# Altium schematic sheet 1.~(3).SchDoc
size 609 x 444 mm
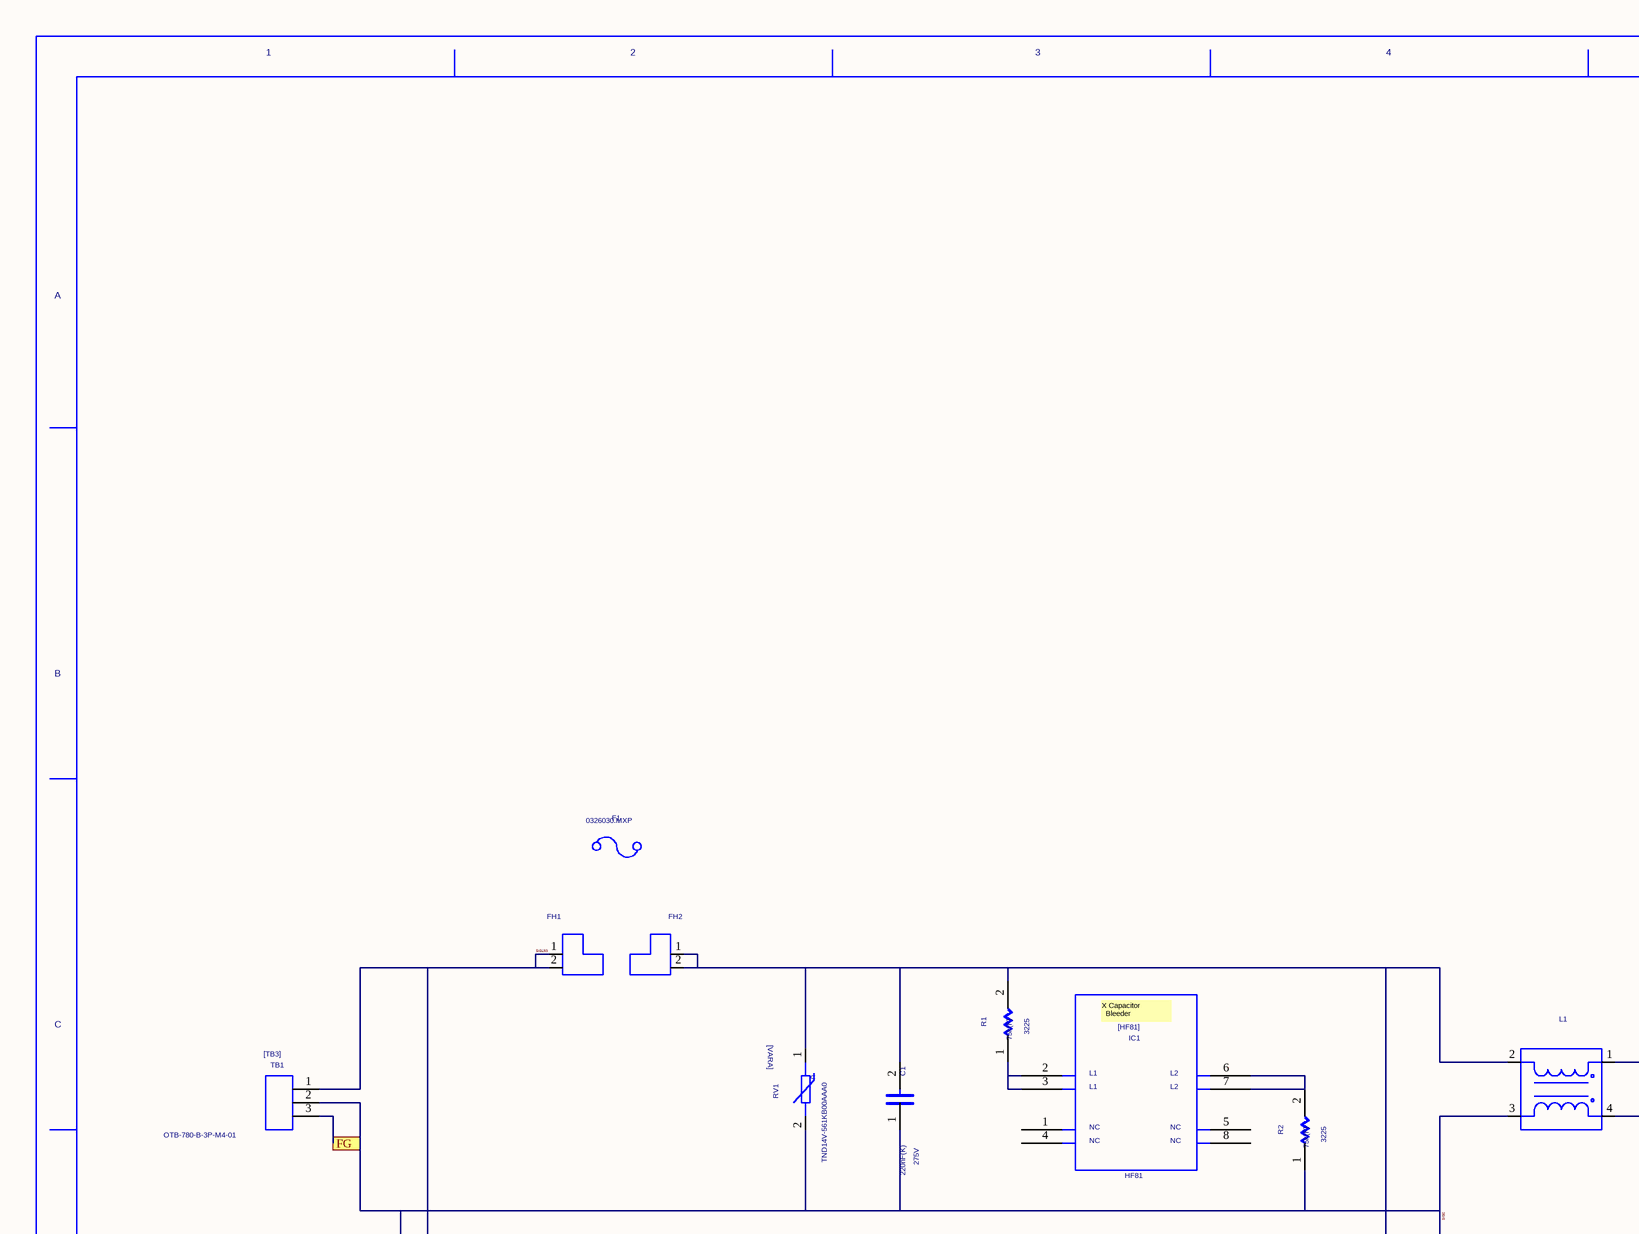
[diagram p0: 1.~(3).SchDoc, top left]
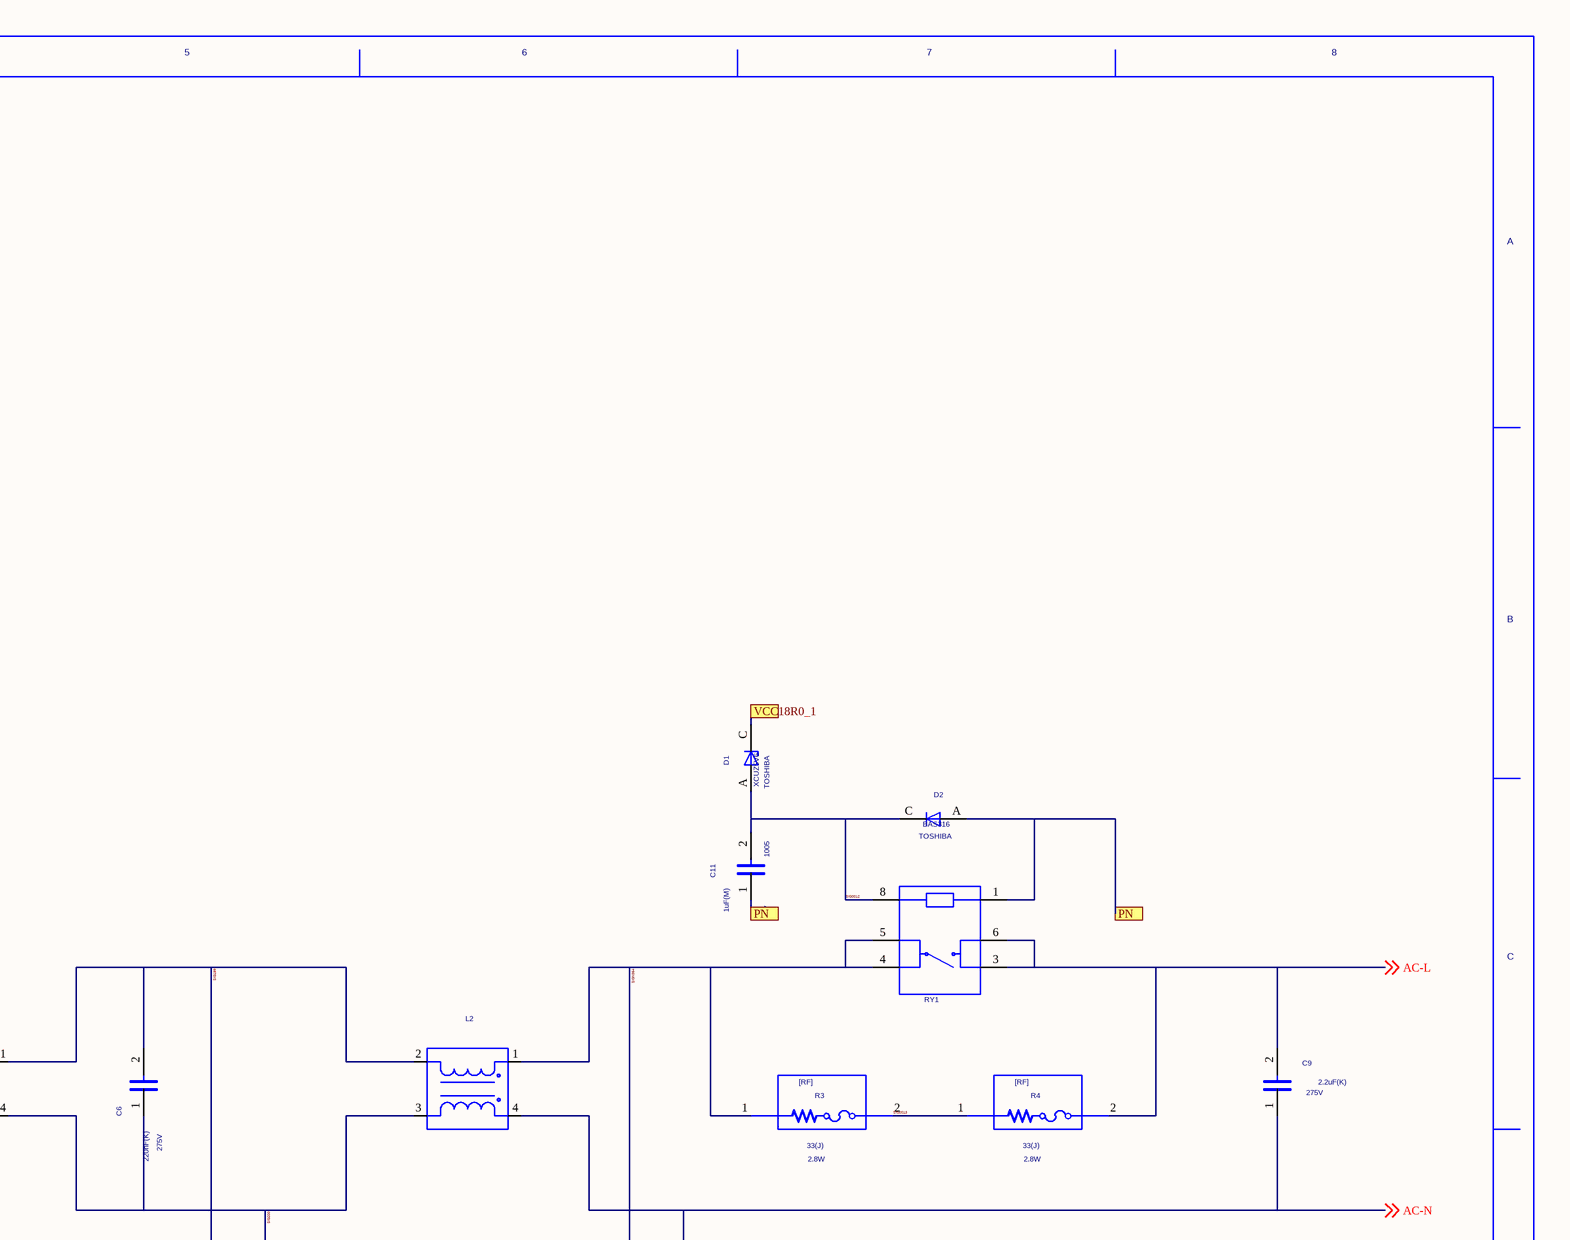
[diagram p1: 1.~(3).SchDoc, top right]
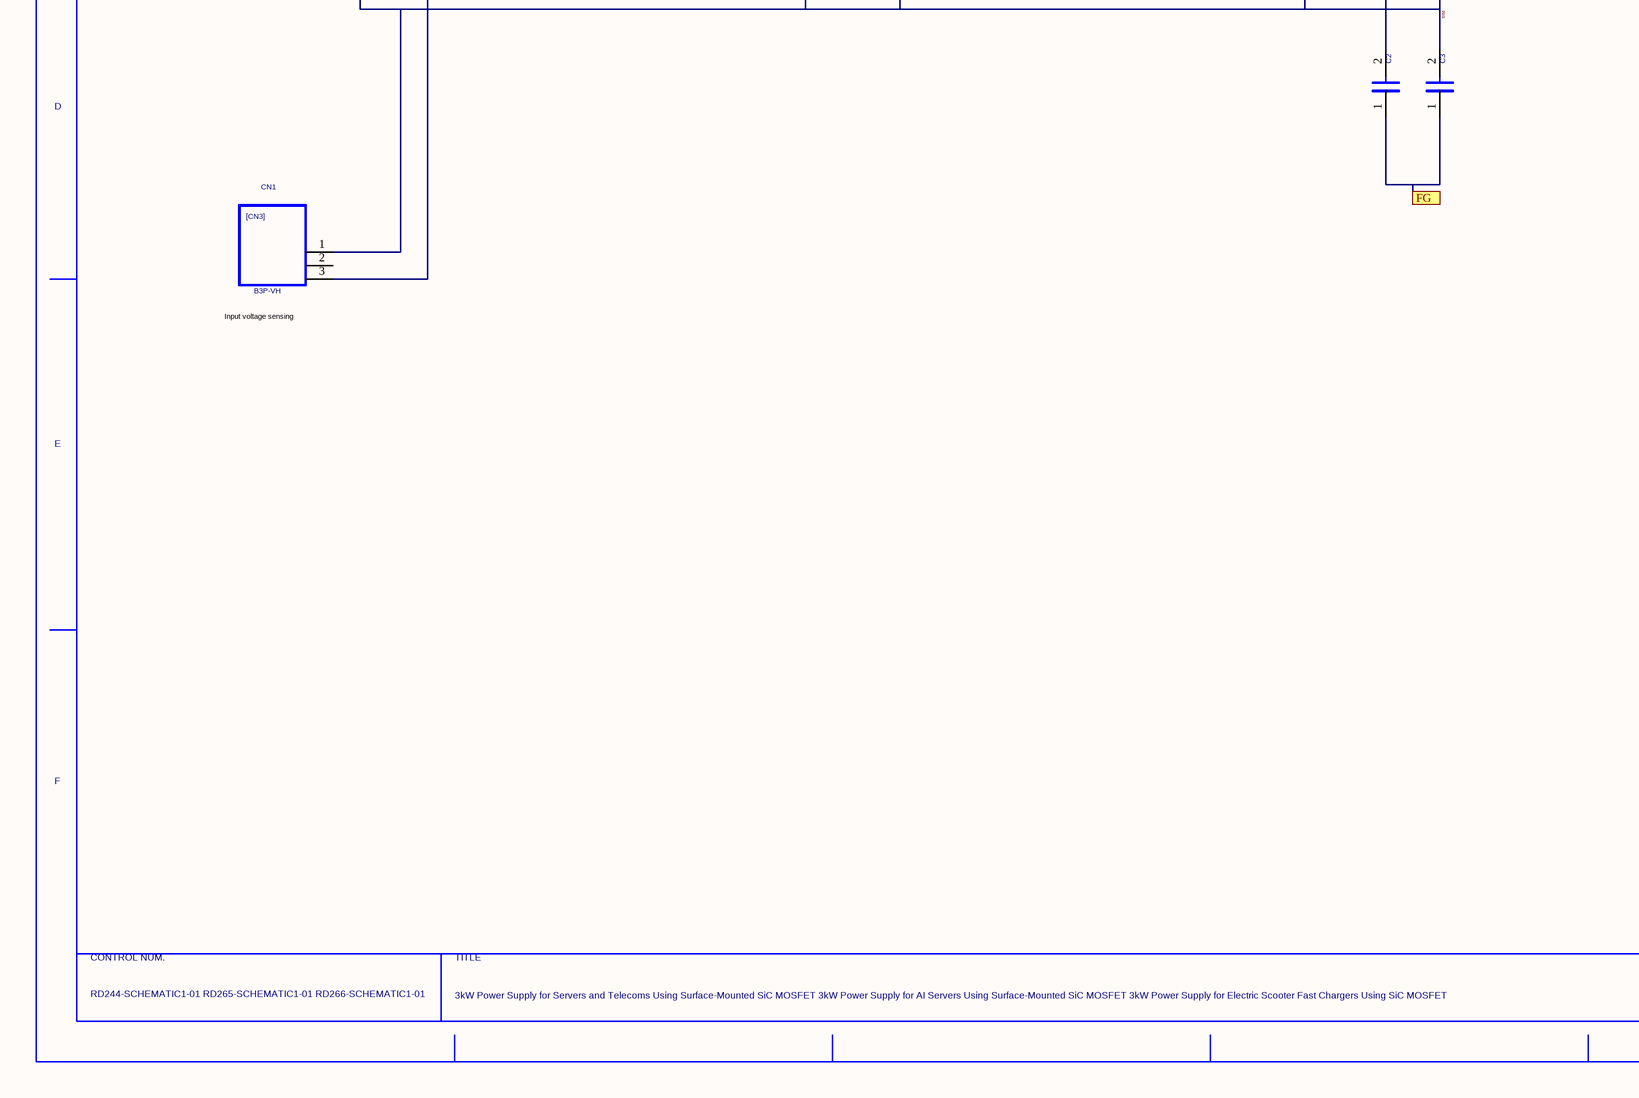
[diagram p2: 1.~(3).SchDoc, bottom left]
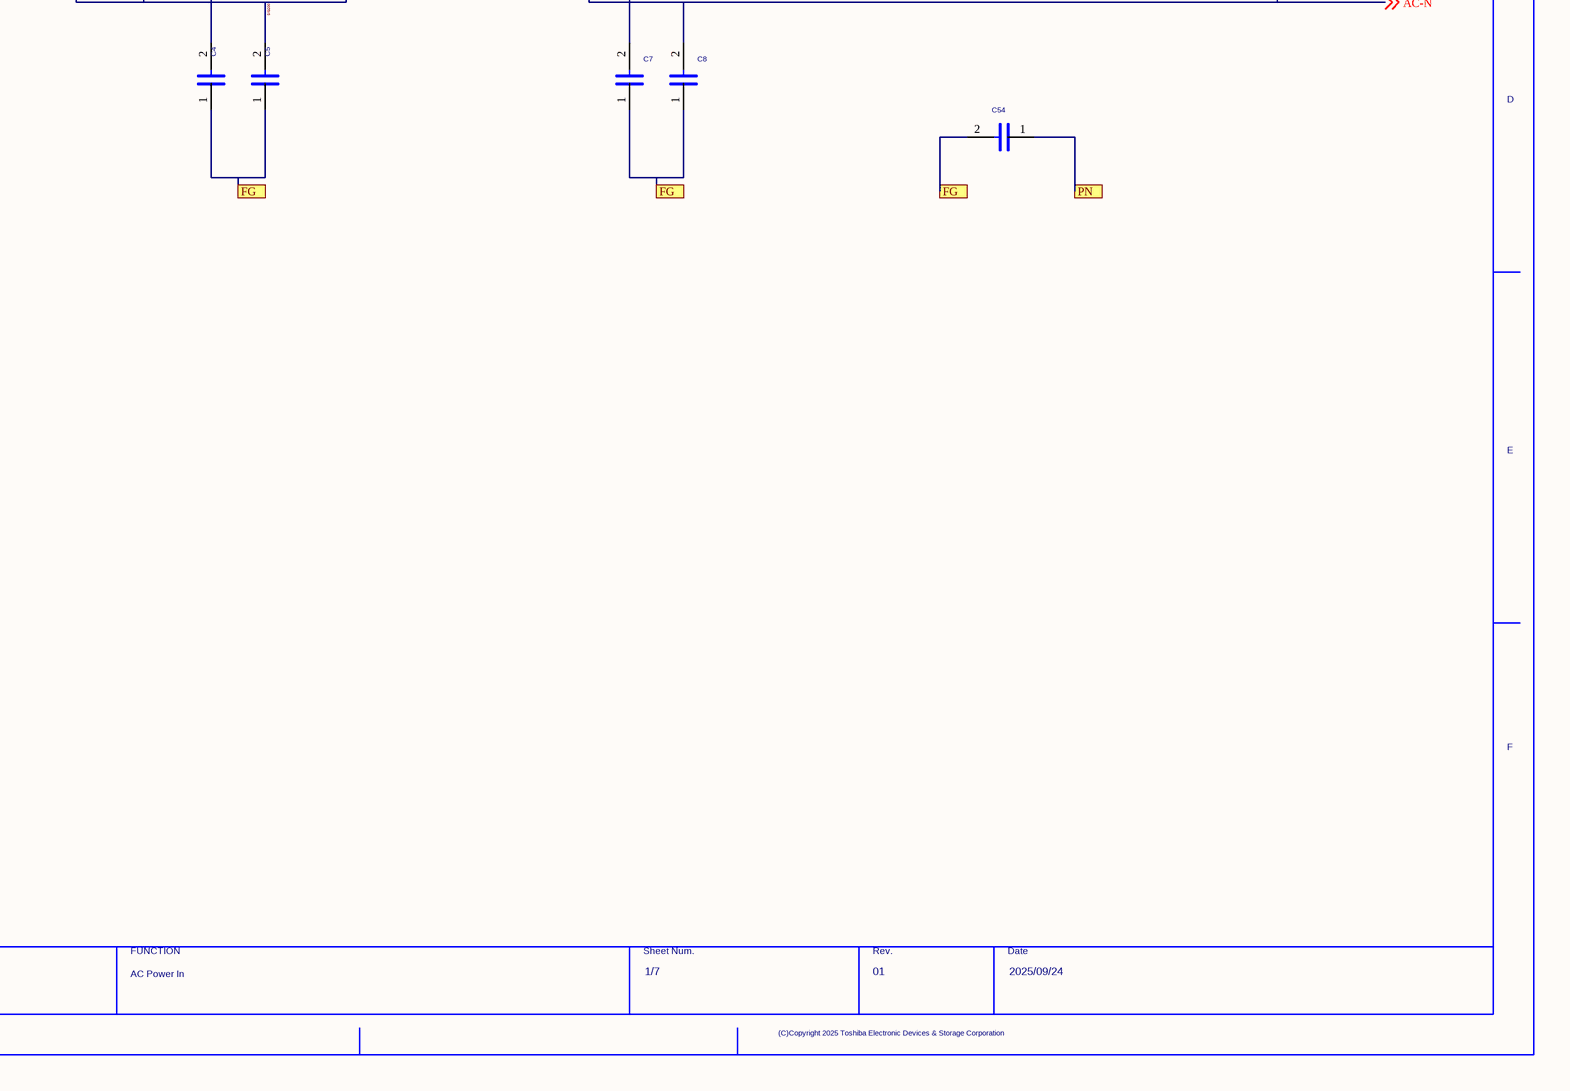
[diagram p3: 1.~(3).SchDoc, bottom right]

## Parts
C1  VAL1: 220nF(K)  VAL2: 275V  (hidden comment: C)
C2  DE2B3SA101KA3BT02F  (value not drawn)
C3  DE2B3SA101KA3BT02F  (value not drawn)
C4  DE2E3SA222MN3AT02F  (value not drawn)
C5  DE2E3SA222MN3AT02F  (value not drawn)
C6  VAL1: 220nF(K)  VAL2: 275V  (hidden comment: C)
C7  DE2E3SA222MN3AT02F  (value not drawn)
C8  DE2E3SA222MN3AT02F  (value not drawn)
C9  VAL1: 2.2uF(K)  VAL2: 275V  (hidden comment: C)
C11  VAL1: 1uF(M)  VAL2: 25V  SIZECODESMD: 1005  (hidden comment: C)
C54  DE2B3SA221KA3BT02F  (value not drawn)
CN1  VAL3: B3P-VH  (hidden comment: CN3)
D1  USERCOMPTEXT3: TOSHIBA  VAL3: XCUZ5V6  (hidden comment: ZenerDiode_USC-01)
D2  USERCOMPTEXT3: TOSHIBA  VAL3: BAS316  (hidden comment: D)
F1  (no value)
FH1  01220083Z  (value not drawn)
FH2  01220083Z  (value not drawn)
IC1  VAL3: HF81  (hidden comment: L81)
L1  LDFW021252YBUV0E  (value not drawn)
L2  LDFW021252YBUV0E  (value not drawn)
R1  VAL1: 75k(F)  SIZECODESMD: 3225  (hidden comment: R)
R2  VAL1: 75k(F)  SIZECODESMD: 3225  (hidden comment: R)
R3  VAL1: 33(J)  VAL2: 2.8W  (hidden comment: Y5JA-330JPTL3_5)
R4  VAL1: 33(J)  VAL2: 2.8W  (hidden comment: Y5JA-330JPTL3_5)
RV1  VAL3: TND14V-561KB00AAA0  (hidden comment: VARA)
RY1  G2RL-1A-E2-CV-HA  (value not drawn)
TB1  VAL3: OTB-780-B-3P-M4-01  (hidden comment: TB3)
U?  DATE: 2025/09/24  DRAWINGNUMBER: RD244-SCHEMATIC1-01 / RD265-SCHEMATIC1-01 / RD266-SCHEMATIC1-01  TITLE: 3kW Power Supply for Servers and Telecoms Using Surface-Mounted SiC MOSFET / 3kW Power Supply for AI Servers Using Surface-Mounted SiC MOSFET / 3kW Power Supply for Electric Scooter Fast Chargers Using SiC MOSFET  FUNCTION: AC Power In  SHEETNUMBER: 1/7  REVISION: 01  (hidden comment: WAKU_DEF_A3_1)

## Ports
FG, PN, VCC18R0_1

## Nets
AC-L: C9.2 R4.2 RY1.3 RY1.6 ; off-sheet AC-L
AC-N: C8.2 C9.1 L2.4 ; off-sheet AC-N
PN: C11.1 C54.1 D2.A RY1.1 ; port PN
SIG1: C1.2 C2.2 FH2.1 FH2.2 L1.2 R1.2 RV1.1
SIG2: C1.1 C2.1 C3.1 C3.2 C4.1 C5.1 C7.1 C8.1 C54.2 CN1.1 L1.3 R2.1 RV1.2 TB1.2 TB1.3 ; port FG
SIG9: IC1.2 IC1.3 R1.1
SIG10: IC1.6 IC1.7 R2.2
SIG0012: C11.2 D1.A D2.C RY1.8
SIG0013: R3.2 R4.1
SIG193: CN1.3 FH1.1 FH1.2 TB1.1
SIG199: C4.2 C6.2 L1.1 L2.2
SIG200: C5.2 C6.1 L1.4 L2.3
SIGN364: C7.2 L2.1 R3.1 RY1.4 RY1.5
VCC18R0_1: D1.C ; port VCC18R0_1

Not connected (* = marked no-connect by the designer): CN1 2; IC1 1 4 5 8

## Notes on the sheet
- (near CN1) Input voltage sensing

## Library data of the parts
C1 C6 = C_Dup2: OriginalSymbolOrigin: (2540,7620); COMP: PRT_17; MAXGCOUNT: 1; SIZECODESMD: DIP; SAVECOUNT: 0
C2 C3 = DE2B3SA101KA3BT02F: VAL1: 100pF; VAL2: 250V; TIME: 18:06:52; UPDATEUSER: t6860224; SAVECOUNT: 1; OriginalSymbolOrigin: (2540,7620); SIZECODESMD: DIP; CHIPSIZE: リードピッチ7.5mm品希望
C4 C7 C8 = DE2E3SA222MN3AT02F: VAL1: 2.2nF(M); VAL2: 250V; TIME: 18:04:40; UPDATEUSER: t6860224; UPDATETIME: 18:05:46; SAVECOUNT: 2; OriginalSymbolOrigin: (2540,7620); CHIPSIZE: リードピッチ7.5mm品希望; MAXGCOUNT: 1; SIZECODESMD: DIP
C5 = DE2E3SA222MN3AT02F: SQ_PART_MODEL: CON_2.2N; VAL1: 2.2nF(M); VAL2: 250V; TIME: 18:04:40; UPDATEUSER: t6860224; UPDATETIME: 18:05:46; SAVECOUNT: 2; OriginalSymbolOrigin: (2540,7620); CHIPSIZE: リードピッチ7.5mm品希望; MAXGCOUNT: 1; SIZECODESMD: DIP; ADSCNVFLAG: ON
C9 = C_Dup2: OriginalSymbolOrigin: (2540,7620); COMP: PRT_18; MAXGCOUNT: 1; SIZECODESMD: DIP; SAVECOUNT: 0
C11 = C_Dup2: OriginalSymbolOrigin: (2540,7620); COMP: PRT_52; MAXGCOUNT: 1; SAVECOUNT: 0
C54 = DE2B3SA221KA3BT02F: VAL1: 220pF(K); VAL2: 250V; TIME: 18:06:26; UPDATEUSER: t6860224; SAVECOUNT: 1; OriginalSymbolOrigin: (2540,7620); SIZECODESMD: DIP
CN1 = CN3: OriginalSymbolOrigin: (2540,17780); USERCOMPTEXT3: ローカライズ; COMPONENTNAME: G36220401068_package; MAXGCOUNT: 1; COMP: G36220401068; ADSCNVFLAG: ON; SAVECOUNT: 0
D1 = ZENERDIODE_USC-01: SAVEAREA0: -4630,-153,17114,13055; TIME: 14:49:55; UPDATEUSER: t4887876; UPDATETIME: 08:23:49; SAVECOUNT: 9; VAL1: 5.6V; OriginalSymbolOrigin: (5080,5080); MAXGCOUNT: 1; ADSCNVFLAG: ON; ADSCOMPONENTNAME: D_ZD
D2 = D_Dup1: SAVEAREA0: -225,-91,12804,7836; SAVECOUNT: 3; TIME: 14:49:55; UPDATEUSER: 19870035; UPDATETIME: 14:20:16; OriginalSymbolOrigin: (5080,5080); USERCOMPTEXT2: 100V,0.25A; COMP: PRT_26; MAXGCOUNT: 1
F1 = 0326030.MXP: PCBCELLNAME: F; SAVECOUNT: 7; SAVEAREA0: -525,-4690,15446,5013; DEVICENAME: F0805B2R00FWTR; VAL1: 250VAC; VAL2: 30A SlowBlow; TIME: 10:50:48; UPDATEUSER: t4887876; UPDATETIME: 10:51:07; OriginalSymbolOrigin: (3048,3166)
FH1 FH2 = 01220083Z: VAL1: 250V; VAL2: 30A; TIME: 10:48:22; UPDATEUSER: t4887876; UPDATETIME: 10:49:44; SAVECOUNT: 3; OriginalSymbolOrigin: (7620,10160)
IC1 = L81: SAVEAREA0: -12429,-3512,55842,41521; TIME: 18:31:00; UPDATEUSER: cae; UPDATETIME: 11:10:50; SAVECOUNT: 13; OriginalSymbolOrigin: (7620,35560); COMP: PRT_45
L1 L2 = LDFW021252YBUV0E: DEVICENAME: DLW21HN670SQ2; SAVEAREA0: -21350,-26515,41553,39372; TIME: 11:39:40; UPDATEUSER: t4887876; UPDATETIME: 20:09:21; SAVECOUNT: 7; VAL1: 8.1mH; VAL2: 21A; OriginalSymbolOrigin: (2540,12700)
R1 R2 = R_Dup2: VAL2: 500mW; OriginalSymbolOrigin: (5080,5080); COMP: PRT_23; MAXGCOUNT: 1; SAVECOUNT: 0
R3 R4 = Y5JA-330JPTL3_5: TIME: 16:26:39; UPDATEUSER: t4887876; UPDATETIME: 20:40:35; SAVECOUNT: 5; OriginalSymbolOrigin: (-1270,12700); MAXGCOUNT: 1; CHIPSIZE: 13x9xH25.5
RV1 = VARA: SAVEAREA0: -9950,-8554,25168,13619; SAVECOUNT: 12; TIME: 09:56:50; UPDATEUSER: tomizawa-y; OriginalSymbolOrigin: (2540,5080); COMP: PRT_37; VAL1: 560V; MAXGCOUNT: 1
RY1 = G2RL-1A-E2-CV-HA: TIME: 17:19:14; UPDATEUSER: t4887876; UPDATETIME: 19:21:58; SAVECOUNT: 7; COMP: G2RL-1A-E2-CV-HA_DC12; OriginalSymbolOrigin: (5080,20320); USERCOMPTEXT1: 23A; MAXGCOUNT: 1; SAVEAREA0: -9347,-440,34039,23986
TB1 = TB3: SAVEAREA0: -8260,-205,20967,17940; TIME: 13:41:39; UPDATEUSER: 19990028; UPDATETIME: 11:31:50; SAVECOUNT: 4; OriginalSymbolOrigin: (2540,12700); USERCOMPTEXT3: ローカライズ; MAXGCOUNT: 1; COMP: K29S000A; ADSCNVFLAG: ON
U? = WAKU_DEF_A3_1: PLOTTIME: HH:MM; SAVEAREA0: 96913,-567914,509243,-368858; TIME: 10:19:22; UPDATEUSER: t5459927; UPDATETIME: 13:12:48; SAVECOUNT: 3; ZONEOFFSETX: 36; ZONEOFFSETY: -24; OriginalSymbolOrigin: (12700,-12700); SHTSAVECOUNT: 118; PAGENUMBER: 1; DESIGNED: TOSHIBA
